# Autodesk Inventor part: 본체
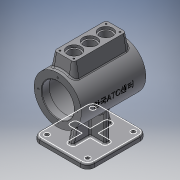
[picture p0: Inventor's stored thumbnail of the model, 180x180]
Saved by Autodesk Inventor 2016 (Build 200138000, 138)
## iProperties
Created: 2015-11
Part Number: 본체
Material: 알루미늄 6061
Document SubType Name: Modeling
Designer: mduedu
Density: 2.71 g/cm^3
Mass: 1489.47 g
Surface Area: 1334.31 cm^2
Volume: 549.619 cm^3
Appearance: 기본값
Author: mduedu
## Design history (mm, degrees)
sketch "스케치2"
  geometry: C1 r 47.5 at (0, 0); 1 further point
  constraints: 1 centre point, 1 coincident
  dimensions: "d147" = 95 diameter of C1
extrude "돌출1" new body sketch "스케치2" stored distance "d12" = 130; taper "d13" = 0 deg
feature "쉘1" dims "d31" = 15, "d32" = 6, "d33" = 15
sketch "스케치5"
  geometry: C1 r 32.5 at (0, 0); 1 further point
  constraints: 1 centre point, 1 coincident
  dimensions: "d34" = 65 diameter of C1
extrude "돌출3" cut sketch "스케치5" stored distance "d36" = 3; taper "d37" = 0 deg
node "작업 평면1"
sketch "스케치6"
  geometry: L1 (-60, -55)-(60, -55); L2 (60, -55)-(60, 55); L3 (60, 55)-(-60, 55); L4 (-60, 55)-(-60, -55); L5 (-60, -55)-(60, 55); L6 (60, -55)-(-60, 55); 1 further point
  constraints: 12 end point, 2 midpoint, 2 parallel, 1 horizontal, 1 perpendicular
  dimensions: "d41" = 110 distance of L3.end L1.start; "d43" = 120 distance of L2.end L3.end
extrude "돌출4" join sketch "스케치6" distance "d44" = 10; taper "d45" = 0 deg
sketch "스케치19"
  geometry: L1 (-5, 35)-(5, 35); L2 (5, 35)-(5, -35); L3 (5, -35)-(-5, -35); L4 (-5, -35)-(-5, 35); L5 (-60, 55)-(-60, -55) reference; L6 (5, -35)-(-5, 35); L7 (5, 35)-(-5, -35); 3 further points
  constraints: 12 end point, 2 midpoint, 2 parallel, 1 coincident, 1 horizontal, 1 horizontal alignment, 1 perpendicular
  dimensions: "d151" = 10 distance of L1.start L1.end; "d152" = 70 distance of L3.end L1.start
extrude "돌출9" join sketch "스케치19" stored distance "d153" = 10; taper "d154" = 0 deg
sketch "스케치20"
  geometry: L1 (65, 32.5)-(50, 32.5) reference; L2 (50, 32.5)-(50, 41.5) reference; L3 (50, 41.5)-(-50, 41.5) reference; L4 (-50, 41.5)-(-50, 32.5) reference; L5 (-50, 32.5)-(-65, 32.5) reference; L6 (-65, 32.5)-(-65, 47.5) reference; L7 (-65, 47.5)-(65, 47.5) reference; L8 (65, 47.5)-(65, 32.5) reference; L9 (50, -32.5)-(65, -32.5) reference; L10 (65, -32.5)-(65, -47.5) reference; L11 (65, -47.5)-(5, -47.5) reference; L12 (5, -47.5)-(5, -90) reference; L13 (5, -90)-(60, -90) reference; L14 (60, -90)-(60, -100) reference; L15 (60, -100)-(-60, -100) reference; L16 (-60, -100)-(-60, -90) reference; L17 (-60, -90)-(-5, -90) reference; L18 (-5, -90)-(-5, -47.5) reference; L19 (-5, -47.5)-(-65, -47.5) reference; L20 (-65, -47.5)-(-65, -32.5) reference; L21 (-65, -32.5)-(-50, -32.5) reference; L22 (-50, -32.5)-(-50, -41.5) reference; L23 (-50, -41.5)-(50, -41.5) reference; L24 (50, -41.5)-(50, -32.5) reference; L25 (-40, -90)-(-28.612, -47.5); 1 further point
  constraints: 2 end point, 2 point on line
  dimensions: "d155" = 20 distance from line of L25.start L16; "d156" = 105 deg angle of L25 L17
feature "리브2" sketch "스케치20" dims "d157" = 1, "d158" = 10, "d159" = 0, "d160" = 0, "d161" = 1, "d162" = 1
fillet "모깎기21" dims "d163" = 3
fillet "모깎기22" dims "d164" = 3
fillet "모깎기23" dims "d165" = 3
sketch "스케치21" dims "d166" = 78
  geometry: 3 further points
  constraints: 2 horizontal alignment, 1 coincident, 2 other
hole "구멍6" sketch "스케치21" at (39, 0) diameter "d168" = 3.242; stored, may be unused: countersink angle "d172" = 90 deg, drill point angle "d174" = 118 deg; dims "d169" = 9, "d170" = 4, "d171" = 2, "d173" = 11
node "작업 평면2"
sketch "스케치13"
  geometry: L1 (-52.5, -20)-(52.5, -20); L2 (52.5, -20)-(52.5, 20); L3 (52.5, 20)-(-52.5, 20); L4 (-52.5, 20)-(-52.5, -20); L5 (-52.5, -20)-(52.5, 20); L6 (52.5, -20)-(-52.5, 20); 1 further point
  constraints: 12 end point, 2 midpoint, 2 parallel, 1 horizontal, 1 perpendicular
  dimensions: "d93" = 105 distance of L2.end L3.end; "d95" = 40 distance of L1.end L2.end
extrude "돌출8" join sketch "스케치13" stored distance "d96" = 80; taper "d97" = 0 deg
fillet "모깎기15" dims "d98" = 5
feature "면 기울기1" dims angle "d178" = 10 deg
fillet "모깎기24" dims "d179" = 3
sketch "스케치14"
  geometry: L1 (-52.5, 15)-(-52.5, -15) reference; L2 (52.5, -15)-(52.5, 15) reference; L3 (-52.5, 0)-(52.5, 0); 4 further points
  constraints: 2 end point, 2 midpoint, 2 point on line, 1 coincident
  dimensions: "d100" = 32 distance of point (-32, 0) point (0, 0); "d102" = 32 distance of point (32, 0) point (0, 0) (derived)
hole "구멍3" sketch "스케치14" at (-32, 0), (0, 0), (32, 0) diameter "d103" = 22; stored, may be unused: countersink angle "d107" = 90 deg, drill point angle "d109" = 118 deg; dims "d104" = 8, "d105" = 28, "d106" = 5, "d108" = 10
sketch "스케치15"
  geometry: L1 (46.5, -14)-(-46.5, -14); L2 (-46.5, -14)-(-46.5, 14); L3 (-46.5, 14)-(46.5, 14); L4 (46.5, 14)-(46.5, -14); L5 (46.5, -14)-(-46.5, 14); L6 (-46.5, -14)-(46.5, 14); L7 (47.5, 20)-(-47.5, 20) reference; L8 (-52.5, 15)-(-52.5, -15) reference; 5 further points
  constraints: 12 end point, 4 coincident, 2 midpoint, 2 parallel, 1 horizontal, 1 perpendicular
  dimensions: "d110" = 6 distance between parallel lines of L3 L7; "d111" = 6 distance between parallel lines of L2 L8
hole "구멍4" sketch "스케치15" at (-46.5, 14), (46.5, 14), (46.5, -14), (-46.5, -14) diameter "d112" = 3.242; stored, may be unused: countersink angle "d116" = 90 deg, drill point angle "d118" = 118 deg; dims "d113" = 10, "d114" = 28, "d115" = 5, "d117" = 13
node "작업 평면3"
sketch "스케치22"
  geometry: 2 further points
  constraints: 1 coincident, 1 other
feature "엠보싱3" sketch "스케치22" dims "d31" = 15, "d181" = 0.5, "d182" = 0
chamfer "모따기2" distance "d183" = 1; stored, may be unused: second distance "d184" = 2, angle "d185" = 45 deg
fillet "모깎기25" dims "d186" = 14
sketch "스케치23"
  geometry: L1 (46, 55)-(-46, 55) reference; L2 (60, -41)-(60, 41) reference; L3 (-46, -55)-(46, -55) reference; L4 (-60, 41)-(-60, -41) reference; A1 r 14 centre (-46, 41) between (-46, 55) and (-60, 41) reference; A2 r 14 centre (46, 41) between (60, 41) and (46, 55) reference; A3 r 14 centre (46, -41) between (46, -55) and (60, -41) reference; A4 r 14 centre (-46, -41) between (-60, -41) and (-46, -55) reference; 1 further point
hole "구멍7" sketch "스케치23" at (-46, 41), (-46, -41), (46, -41), (46, 41) diameter "d187" = 6; stored, may be unused: countersink angle "d191" = 90 deg, drill point angle "d193" = 118 deg; dims "d188" = 9, "d189" = 10, "d190" = 2, "d192" = 11
fillet "모깎기26" dims "d194" = 3
node "솔리드1"
mirror "대칭6"
pattern_circular "원형 패턴2" dims angle "d176" = 360 deg
mirror "대칭5"
node "투영된 루프2"
node "절단 모서리 투영1"
